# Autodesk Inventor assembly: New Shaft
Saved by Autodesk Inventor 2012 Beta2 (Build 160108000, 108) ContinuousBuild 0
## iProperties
Created: 2011-01
Part Number: New Shaft
Document SubType Name: Assembly
Designer: Beta-8540w
ClientObjectVersion: 1
Author: Beta-8540w
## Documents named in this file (2)
- C:\Inventor 2012 Essentials\Assemblies\Chapter 8\Design Accelerators\Shaft c8-05.iam
- C:\Inventor 2012 Essentials\Assemblies\Chapter 8\Design Accelerators\Shaft c8-05.ipt
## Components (1 placed, 1 different names)
1. New Shaft:1
